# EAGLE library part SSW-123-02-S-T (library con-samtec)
THROUGH-HOLE .025" SQ POST SOCKET Source: Samtec SSW.pdf
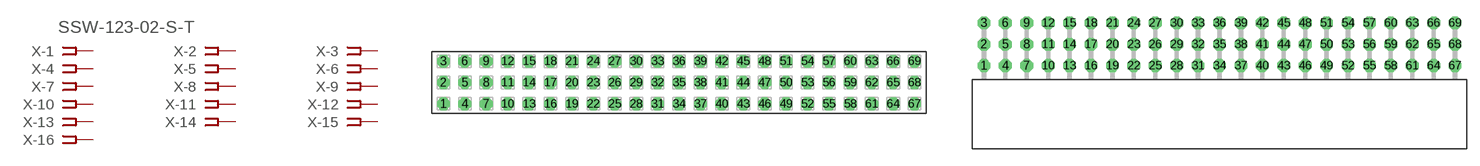
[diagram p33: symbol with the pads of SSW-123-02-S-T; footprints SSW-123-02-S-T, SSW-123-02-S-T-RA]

Designator prefix X; gates -1=FPINV -2=FPIN -3=FPIN -4=FPIN -5=FPIN -6=FPIN -7=FPIN -8=FPIN -9=FPIN -10=FPIN -11=FPIN -12=FPIN -13=FPIN -14=FPIN -15=FPIN -16=FPIN -17=FPIN -18=FPIN -19=FPIN -20=FPIN -21=FPIN -22=FPIN -23=FPIN -24=FPIN -25=FPIN -26=FPIN -27=FPIN -28=FPIN -29=FPIN -30=FPIN -31=FPIN -32=FPIN -33=FPIN -34=FPIN -35=FPIN -36=FPIN -37=FPIN -38=FPIN -39=FPIN -40=FPIN -41=FPIN -42=FPIN -43=FPIN -44=FPIN -45=FPIN -46=FPIN -47=FPIN -48=FPIN -49=FPIN -50=FPIN -51=FPIN -52=FPIN -53=FPIN -54=FPIN -55=FPIN -56=FPIN -57=FPIN -58=FPIN -59=FPIN -60=FPIN -61=FPIN -62=FPIN -63=FPIN -64=FPIN -65=FPIN -66=FPIN -67=FPIN -68=FPIN -69=FPIN

## SSW-123-02-S-T (OC_FARNELL: unknown; OC_NEWARK: unknown)  [SSW-123-02-S-T]
1  -1:1  pas
2  -2:1  pas
3  -3:1  pas
4  -4:1  pas
5  -5:1  pas
6  -6:1  pas
7  -7:1  pas
8  -8:1  pas
9  -9:1  pas
10  -10:1  pas
11  -11:1  pas
12  -12:1  pas
13  -13:1  pas
14  -14:1  pas
15  -15:1  pas
16  -16:1  pas
17  -17:1  pas
18  -18:1  pas
19  -19:1  pas
20  -20:1  pas
21  -21:1  pas
22  -22:1  pas
23  -23:1  pas
24  -24:1  pas
25  -25:1  pas
26  -26:1  pas
27  -27:1  pas
28  -28:1  pas
29  -29:1  pas
30  -30:1  pas
31  -31:1  pas
32  -32:1  pas
33  -33:1  pas
34  -34:1  pas
35  -35:1  pas
36  -36:1  pas
37  -37:1  pas
38  -38:1  pas
39  -39:1  pas
40  -40:1  pas
41  -41:1  pas
42  -42:1  pas
43  -43:1  pas
44  -44:1  pas
45  -45:1  pas
46  -46:1  pas
47  -47:1  pas
48  -48:1  pas
49  -49:1  pas
50  -50:1  pas
51  -51:1  pas
52  -52:1  pas
53  -53:1  pas
54  -54:1  pas
55  -55:1  pas
56  -56:1  pas
57  -57:1  pas
58  -58:1  pas
59  -59:1  pas
60  -60:1  pas
61  -61:1  pas
62  -62:1  pas
63  -63:1  pas
64  -64:1  pas
65  -65:1  pas
66  -66:1  pas
67  -67:1  pas
68  -68:1  pas
69  -69:1  pas

## SSW-123-02-S-TRA (MPN: SSW-123-02-S-T-RA; OC_FARNELL: unknown; OC_NEWARK: 82P8952)  [SSW-123-02-S-T-RA]
Pads as for SSW-123-02-S-T

## Footprint SSW-123-02-S-T (pad centres in mm)
THROUGH-HOLE .025" SQ POST SOCKET Source: Samtec SSW.pdf
drill 1 pad 1.5 octagon: 1 -27.94,-2.54; 2 -27.94,0; 3 -27.94,2.54; 4 -25.4,-2.54; 5 -25.4,0; 6 -25.4,2.54; 7 -22.86,-2.54; 8 -22.86,0; 9 -22.86,2.54; 10 -20.32,-2.54; 11 -20.32,0; 12 -20.32,2.54; 13 -17.78,-2.54; 14 -17.78,0; 15 -17.78,2.54; 16 -15.24,-2.54; 17 -15.24,0; 18 -15.24,2.54; 19 -12.7,-2.54; 20 -12.7,0; 21 -12.7,2.54; 22 -10.16,-2.54; 23 -10.16,0; 24 -10.16,2.54; 25 -7.62,-2.54; 26 -7.62,0; 27 -7.62,2.54; 28 -5.08,-2.54; 29 -5.08,0; 30 -5.08,2.54; 31 -2.54,-2.54; 32 -2.54,0; 33 -2.54,2.54; 34 0,-2.54; 35 0,0; 36 0,2.54; 37 2.54,-2.54; 38 2.54,0; 39 2.54,2.54; 40 5.08,-2.54; 41 5.08,0; 42 5.08,2.54; 43 7.62,-2.54; 44 7.62,0; 45 7.62,2.54; 46 10.16,-2.54; 47 10.16,0; 48 10.16,2.54; 49 12.7,-2.54; 50 12.7,0; 51 12.7,2.54; 52 15.24,-2.54; 53 15.24,0; 54 15.24,2.54; 55 17.78,-2.54; 56 17.78,0; 57 17.78,2.54; 58 20.32,-2.54; 59 20.32,0; 60 20.32,2.54; 61 22.86,-2.54; 62 22.86,0; 63 22.86,2.54; 64 25.4,-2.54; 65 25.4,0; 66 25.4,2.54; 67 27.94,-2.54; 68 27.94,0; 69 27.94,2.54

## Footprint SSW-123-02-S-T-RA (pad centres in mm)
THROUGH-HOLE .025" SQ POST SOCKET Source: Samtec SSW.pdf
drill 1 pad 1.5 octagon: 1 -27.94,1.524; 2 -27.94,4.064; 3 -27.94,6.604; 4 -25.4,1.524; 5 -25.4,4.064; 6 -25.4,6.604; 7 -22.86,1.524; 8 -22.86,4.064; 9 -22.86,6.604; 10 -20.32,1.524; 11 -20.32,4.064; 12 -20.32,6.604; 13 -17.78,1.524; 14 -17.78,4.064; 15 -17.78,6.604; 16 -15.24,1.524; 17 -15.24,4.064; 18 -15.24,6.604; 19 -12.7,1.524; 20 -12.7,4.064; 21 -12.7,6.604; 22 -10.16,1.524; 23 -10.16,4.064; 24 -10.16,6.604; 25 -7.62,1.524; 26 -7.62,4.064; 27 -7.62,6.604; 28 -5.08,1.524; 29 -5.08,4.064; 30 -5.08,6.604; 31 -2.54,1.524; 32 -2.54,4.064; 33 -2.54,6.604; 34 0,1.524; 35 0,4.064; 36 0,6.604; 37 2.54,1.524; 38 2.54,4.064; 39 2.54,6.604; 40 5.08,1.524; 41 5.08,4.064; 42 5.08,6.604; 43 7.62,1.524; 44 7.62,4.064; 45 7.62,6.604; 46 10.16,1.524; 47 10.16,4.064; 48 10.16,6.604; 49 12.7,1.524; 50 12.7,4.064; 51 12.7,6.604; 52 15.24,1.524; 53 15.24,4.064; 54 15.24,6.604; 55 17.78,1.524; 56 17.78,4.064; 57 17.78,6.604; 58 20.32,1.524; 59 20.32,4.064; 60 20.32,6.604; 61 22.86,1.524; 62 22.86,4.064; 63 22.86,6.604; 64 25.4,1.524; 65 25.4,4.064; 66 25.4,6.604; 67 27.94,1.524; 68 27.94,4.064; 69 27.94,6.604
